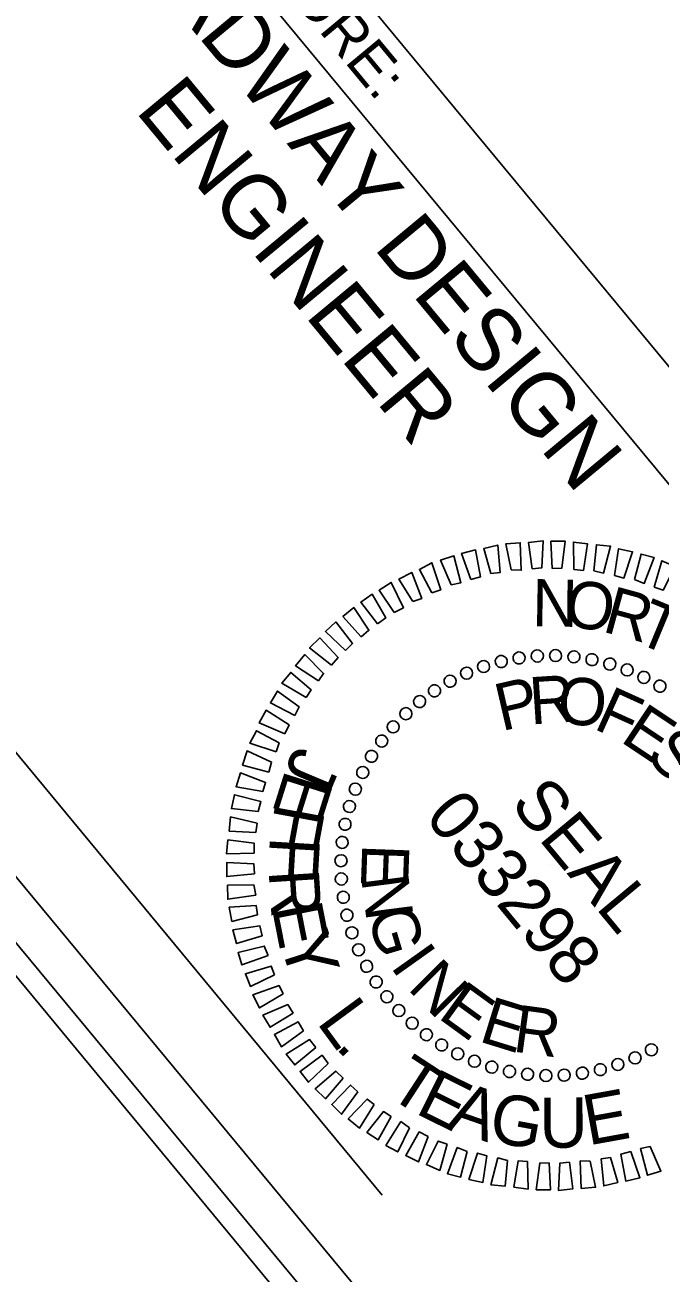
# Model space of a CAD drawing. Extents: x 2054826 to 2060231, y 685508 to 690809.
# Drawn here: x 2058686.8 to 2058800.7, y 687644.8 to 687868.3 of the extents above; entities that cross this region are included whole.
import ezdxf

# ---------------------------------------------------------------- set-up
doc = ezdxf.new("R2010")
doc.units = 0
for name, color, linetype in [('Sheet Plot Border Inside CELL', 7, 'Continuous'), ('Sheet Professional Seal CELL', 7, 'Continuous'), ('Sheet Title CELL', 7, 'Continuous')]:
    doc.layers.add(name, color=color, linetype=linetype)

msp = doc.modelspace()

# ---------------------------------------------------------------- linework, layer by layer
at = {"layer": 'Sheet Plot Border Inside CELL'}
msp.add_lwpolyline([(2057387.09, 689263.34), (2058982.75, 687339.12), (2060201.02, 688349.37), (2058605.36, 690273.59)], close=True, dxfattribs=at)
at = {"layer": 'Sheet Professional Seal CELL'}
for p, q in [((2058778.69, 687755.32), (2058778.69, 687755.32)), ((2058782, 687755.44), (2058782, 687755.44)), ((2058785.23, 687755.19), (2058785.23, 687755.19)), ((2058769.04, 687753.45), (2058769.04, 687753.45)), ((2058772.21, 687754.33), (2058772.21, 687754.33)), ((2058775.42, 687755.04), (2058775.42, 687755.04)), ((2058788.54, 687754.72), (2058788.54, 687754.72)), ((2058791.66, 687753.9), (2058791.66, 687753.9)), ((2058763.09, 687750.76), (2058763.09, 687750.76)), ((2058765.94, 687752.25), (2058765.94, 687752.25)), ((2058794.81, 687752.8), (2058794.81, 687752.8)), ((2058797.83, 687751.51), (2058797.83, 687751.51)), ((2058760.27, 687749.1), (2058760.27, 687749.1)), ((2058800.67, 687749.97), (2058800.67, 687749.97)), ((2058757.58, 687747.17), (2058757.58, 687747.17)), ((2058755.09, 687745.01), (2058755.09, 687745.01)), ((2058752.9, 687742.6), (2058752.9, 687742.6)), ((2058750.74, 687740.03), (2058750.74, 687740.03)), ((2058748.89, 687737.33), (2058748.89, 687737.33)), ((2058747.35, 687734.49), (2058747.35, 687734.49)), ((2058746.05, 687731.47), (2058746.05, 687731.47)), ((2058744.96, 687728.32), (2058744.96, 687728.32)), ((2058744.14, 687725.2), (2058744.14, 687725.2)), ((2058743.67, 687721.89), (2058743.67, 687721.89)), ((2058743.42, 687718.66), (2058743.42, 687718.66)), ((2058781.1, 687717.76), (2058781.1, 687717.76)), ((2058743.54, 687715.35), (2058743.54, 687715.35)), ((2058743.82, 687712.08), (2058743.82, 687712.08)), ((2058744.53, 687708.87), (2058744.53, 687708.87)), ((2058745.4, 687705.7), (2058745.4, 687705.7)), ((2058746.61, 687702.6), (2058746.61, 687702.6)), ((2058748.1, 687699.75), (2058748.1, 687699.75)), ((2058749.75, 687696.93), (2058749.75, 687696.93)), ((2058751.68, 687694.24), (2058751.68, 687694.24)), ((2058753.85, 687691.75), (2058753.85, 687691.75)), ((2058756.25, 687689.56), (2058756.25, 687689.56)), ((2058758.82, 687687.4), (2058758.82, 687687.4)), ((2058761.53, 687685.55), (2058761.53, 687685.55)), ((2058764.36, 687684.01), (2058764.36, 687684.01)), ((2058799.11, 687684.76), (2058799.11, 687684.76)), ((2058767.39, 687682.71), (2058767.39, 687682.71)), ((2058770.53, 687681.62), (2058770.53, 687681.62)), ((2058793.16, 687682.06), (2058793.16, 687682.06)), ((2058796.25, 687683.27), (2058796.25, 687683.27)), ((2058773.65, 687680.79), (2058773.65, 687680.79)), ((2058776.96, 687680.33), (2058776.96, 687680.33)), ((2058780.19, 687680.08), (2058780.19, 687680.08)), ((2058783.5, 687680.19), (2058783.5, 687680.19)), ((2058786.78, 687680.48), (2058786.78, 687680.48)), ((2058789.99, 687681.19), (2058789.99, 687681.19))]:
    msp.add_line(p, q, dxfattribs=at)
for points in [[(2058774, 687770.72), (2058773.06, 687775.39), (2058775.63, 687775.58), (2058775.81, 687770.66)], [(2058777.75, 687770.91), (2058777.13, 687775.65), (2058779.71, 687775.94), (2058779.47, 687771.07)], [(2058781.38, 687770.99), (2058781.14, 687775.86), (2058783.7, 687775.84), (2058783.09, 687771.05)], [(2058785.25, 687770.79), (2058785.17, 687775.7), (2058787.7, 687775.36), (2058786.94, 687770.64)], [(2058763.26, 687768.05), (2058761.33, 687772.49), (2058763.74, 687773.23), (2058765, 687768.42)], [(2058766.76, 687769), (2058765.12, 687773.68), (2058767.63, 687774.3), (2058768.51, 687769.48)], [(2058770.37, 687770.05), (2058769.09, 687774.54), (2058771.59, 687775.16), (2058772.04, 687770.27)], [(2058788.85, 687770.56), (2058789.28, 687775.21), (2058791.82, 687774.97), (2058790.57, 687770.14)], [(2058792.55, 687769.74), (2058793.27, 687774.52), (2058795.77, 687773.97), (2058794.21, 687769.26)], [(2058796.11, 687768.98), (2058797.28, 687773.56), (2058799.62, 687772.97), (2058797.85, 687768.29)], [(2058759.77, 687766.62), (2058757.55, 687770.82), (2058759.8, 687772), (2058761.37, 687767.16)], [(2058799.66, 687767.64), (2058801, 687772.36), (2058803.41, 687771.34), (2058801.26, 687767.11)], [(2058756.38, 687765.07), (2058753.87, 687769.03), (2058756.17, 687770.26), (2058757.97, 687765.62)], [(2058750.04, 687761.08), (2058747.04, 687764.93), (2058749.05, 687766.4), (2058751.52, 687762.12)], [(2058753.05, 687763.09), (2058750.33, 687767.07), (2058752.49, 687768.47), (2058754.68, 687763.95)], [(2058747.11, 687758.75), (2058743.82, 687762.36), (2058745.78, 687763.98), (2058748.49, 687759.9)], [(2058744.27, 687756.3), (2058740.69, 687759.67), (2058742.56, 687761.41), (2058745.56, 687757.56)], [(2058741.78, 687753.65), (2058737.86, 687756.73), (2058739.68, 687758.53), (2058742.98, 687755.03)], [(2058739.44, 687750.83), (2058735.33, 687753.56), (2058737.01, 687755.54), (2058740.37, 687752.19)], [(2058737.25, 687747.84), (2058732.86, 687750.44), (2058734.47, 687752.36), (2058738.12, 687749.25)], [(2058735.24, 687744.62), (2058730.82, 687746.9), (2058732.08, 687749.02), (2058735.98, 687746.2)], [(2058733.39, 687741.33), (2058728.83, 687743.3), (2058730.06, 687745.58), (2058734.18, 687742.96)], [(2058731.87, 687738.12), (2058727.16, 687739.68), (2058728.33, 687741.91), (2058732.39, 687739.72)], [(2058730.57, 687734.51), (2058725.84, 687735.75), (2058726.66, 687738.29), (2058731.05, 687736.28)], [(2058729.45, 687731.05), (2058724.68, 687731.87), (2058725.44, 687734.35), (2058729.97, 687732.65)], [(2058728.63, 687727.45), (2058723.83, 687727.95), (2058724.39, 687730.45), (2058729.12, 687729.21)], [(2058728.23, 687723.7), (2058723.46, 687723.94), (2058723.69, 687726.47), (2058728.43, 687725.34)], [(2058727.93, 687719.95), (2058722.97, 687719.83), (2058723.2, 687722.36), (2058727.89, 687721.77)], [(2058727.96, 687716.27), (2058723.01, 687715.78), (2058723.04, 687718.33), (2058727.86, 687718.04)], [(2058728.19, 687712.47), (2058723.17, 687711.71), (2058723.14, 687714.22), (2058727.83, 687714.31)], [(2058728.5, 687708.92), (2058723.92, 687707.75), (2058723.46, 687710.3), (2058728.28, 687710.6)], [(2058729.38, 687705.17), (2058724.77, 687703.79), (2058724.1, 687706.25), (2058728.96, 687706.96)], [(2058730.43, 687701.66), (2058725.69, 687699.97), (2058725.05, 687702.16), (2058729.74, 687703.32)], [(2058731.55, 687698.2), (2058727.25, 687696.1), (2058726.34, 687698.37), (2058730.95, 687699.75)], [(2058733.1, 687694.81), (2058728.86, 687692.27), (2058727.7, 687694.62), (2058732.38, 687696.26)], [(2058734.9, 687691.34), (2058730.78, 687688.79), (2058729.48, 687690.94), (2058733.93, 687692.87)], [(2058736.74, 687688.18), (2058732.79, 687685.3), (2058731.56, 687687.49), (2058735.82, 687689.76)], [(2058738.96, 687685.15), (2058735.21, 687682.04), (2058733.68, 687683.99), (2058737.87, 687686.59)], [(2058741.2, 687682.33), (2058737.69, 687678.93), (2058736.16, 687680.89), (2058740.11, 687683.77)], [(2058743.88, 687679.69), (2058740.71, 687675.99), (2058738.85, 687677.76), (2058742.56, 687680.93)], [(2058746.53, 687677.2), (2058743.6, 687673.21), (2058741.84, 687674.98), (2058745.2, 687678.44)], [(2058749.46, 687674.96), (2058746.83, 687670.73), (2058744.79, 687672.36), (2058748.16, 687675.93)], [(2058752.51, 687672.81), (2058750.14, 687668.61), (2058748.14, 687669.97), (2058751.1, 687673.69)], [(2058755.78, 687670.75), (2058753.67, 687666.47), (2058751.54, 687667.63), (2058754.23, 687671.9)], [(2058759.1, 687669.21), (2058757.39, 687664.68), (2058755.1, 687665.8), (2058757.52, 687670.05)], [(2058762.54, 687667.88), (2058761.19, 687663.16), (2058758.79, 687664.18), (2058760.94, 687668.4)], [(2058766.09, 687666.53), (2058764.92, 687661.96), (2058762.57, 687662.55), (2058764.34, 687667.23)], [(2058769.64, 687665.78), (2058768.93, 687661), (2058766.42, 687661.55), (2058767.98, 687666.25)], [(2058795.44, 687666.51), (2058797.08, 687661.83), (2058794.57, 687661.21), (2058793.69, 687666.04)], [(2058798.93, 687667.46), (2058800.86, 687663.02), (2058798.45, 687662.29), (2058797.19, 687667.09)], [(2058773.35, 687664.95), (2058772.91, 687660.3), (2058770.38, 687660.54), (2058771.63, 687665.38)], [(2058776.95, 687664.72), (2058777.02, 687659.81), (2058774.5, 687660.16), (2058775.26, 687664.88)], [(2058780.82, 687664.52), (2058781.05, 687659.65), (2058778.5, 687659.68), (2058779.11, 687664.47)], [(2058784.45, 687664.61), (2058785.07, 687659.86), (2058782.48, 687659.57), (2058782.73, 687664.45)], [(2058788.19, 687664.79), (2058789.14, 687660.12), (2058786.57, 687659.94), (2058786.39, 687664.85)], [(2058791.82, 687665.46), (2058793.11, 687660.98), (2058790.6, 687660.36), (2058790.15, 687665.25)]]:
    msp.add_lwpolyline(points, close=True, dxfattribs=at)
for centre, major_axis in [((2058772.21, 687754.31), (-0.26, 1.05)), ((2058775.43, 687754.95), (-0.16, 1.07)), ((2058778.69, 687755.3), (-0.07, 1.08)), ((2058781.97, 687755.37), (0.03, 1.08)), ((2058785.25, 687755.15), (0.12, 1.07)), ((2058788.49, 687754.64), (0.21, 1.06)), ((2058766, 687752.21), (-0.434, 0.989)), ((2058769.06, 687753.4), (-0.35, 1.02)), ((2058791.68, 687753.86), (0.3, 1.04)), ((2058794.78, 687752.8), (0.39, 1.01)), ((2058763.05, 687750.77), (-0.518, 0.948)), ((2058797.79, 687751.47), (0.479, 0.968)), ((2058800.66, 687749.89), (0.562, 0.922)), ((2058760.24, 687749.07), (-0.599, 0.899)), ((2058757.59, 687747.13), (-0.675, 0.843)), ((2058755.12, 687744.97), (-0.746, 0.781)), ((2058752.85, 687742.6), (-0.811, 0.713)), ((2058750.79, 687740.05), (-0.87, 0.64)), ((2058748.96, 687737.32), (-0.922, 0.562)), ((2058747.38, 687734.44), (-0.968, 0.479)), ((2058746.06, 687731.44), (-1.01, 0.39)), ((2058745, 687728.34), (-1.04, 0.3)), ((2058744.21, 687725.15), (-1.06, 0.21)), ((2058743.71, 687721.91), (-1.07, 0.12)), ((2058743.49, 687718.63), (-1.08, 0.03)), ((2058743.55, 687715.35), (-1.08, -0.07)), ((2058743.91, 687712.09), (-1.07, -0.16)), ((2058744.54, 687708.87), (-1.05, -0.26)), ((2058745.46, 687705.72), (-1.02, -0.35)), ((2058746.64, 687702.66), (-0.989, -0.434)), ((2058748.09, 687699.71), (-0.948, -0.518)), ((2058749.79, 687696.9), (-0.899, -0.599)), ((2058751.72, 687694.25), (-0.843, -0.675)), ((2058753.88, 687691.78), (-0.781, -0.746)), ((2058756.25, 687689.51), (-0.713, -0.811)), ((2058758.81, 687687.45), (-0.64, -0.87)), ((2058761.53, 687685.62), (-0.562, -0.922)), ((2058799.14, 687684.75), (0.518, -0.948)), ((2058764.41, 687684.04), (-0.479, -0.968)), ((2058767.41, 687682.71), (-0.39, -1.01)), ((2058796.2, 687683.3), (0.434, -0.989)), ((2058770.52, 687681.66), (-0.3, -1.04)), ((2058773.7, 687680.87), (-0.21, -1.06)), ((2058776.95, 687680.37), (-0.12, -1.07)), ((2058786.77, 687680.57), (0.16, -1.07)), ((2058789.99, 687681.2), (0.26, -1.05)), ((2058793.14, 687682.12), (0.35, -1.02)), ((2058780.22, 687680.15), (-0.03, -1.08)), ((2058783.5, 687680.21), (0.07, -1.08))]:
    msp.add_ellipse(centre, major_axis=major_axis, ratio=0.999708, dxfattribs=at)
at = {"layer": 'Sheet Title CELL'}
for p, q in [((2058714.94, 687912.46), (2058854.25, 687744.46)), ((2058699.6, 687909.89), (2058910.89, 687655.09)), ((2058611.54, 687826.74), (2058750.85, 687658.72))]:
    msp.add_line(p, q, dxfattribs=at)
for points in [[(2057547.07, 689076.42), (2058964.15, 687367.54)], [(2058606.09, 687811.11), (2058797.38, 687580.44)]]:
    msp.add_lwpolyline(points, dxfattribs=at)

# ---------------------------------------------------------------- texts
at = {"layer": 'Sheet Professional Seal CELL'}
for s, height, rotation, p in [('N', 8.46, 359.0907, (2058777.7, 687760.63)), ('O', 8.46, 351.8889, (2058783.25, 687760.75)), ('R', 8.46, 344.6877, (2058790.13, 687759.74)), ('T', 8.46, 337.487, (2058795.93, 687757.92)), ('P', 8.46, 13.0661, (2058772.26, 687741.8)), ('R', 8.46, 3.7069, (2058777.49, 687743.02)), ('O', 8.46, 354.3484, (2058781.99, 687743.35)), ('F', 8.46, 335.6342, (2058788.56, 687742.36)), ('E', 8.46, 326.2783, (2058793.36, 687740.1)), ('S', 8.46, 316.9228, (2058797.87, 687737.12)), ('J', 9, 247.2287, (2058735.38, 687739.46)), ('E', 9, 252.4865, (2058733.59, 687735.18)), ('SEAL', 8.997, 309.6672, (2058773.65, 687728.73)), ('033298', 8.997, 309.6672, (2058758.3, 687726.43)), ('F', 9, 259.5958, (2058731.8, 687729.17)), ('F', 9, 266.6124, (2058730.77, 687723.06)), ('E', 8.46, 267.9441, (2058747.32, 687721.71)), ('R', 9, 273.629, (2058730.5, 687716.87)), ('N', 8.46, 277.3012, (2058747.08, 687715.66)), ('E', 9, 281.1093, (2058731.05, 687710.29)), ('G', 8.46, 286.6574, (2058748.12, 687709.12)), ('Y', 9, 288.2186, (2058732.36, 687704.16)), ('I', 8.46, 305.3684, (2058752.2, 687699.74)), ('N', 8.46, 314.7236, (2058755.23, 687695.72)), ('E', 8.46, 324.079, (2058760.66, 687690.58)), ('L', 9, 306.332, (2058739, 687689.68)), ('E', 8.46, 342.7913, (2058767.99, 687686.33)), ('R', 8.46, 352.1486, (2058774.1, 687684.48)), ('.', 9, 312.6068, (2058742.32, 687685.24)), ('T', 9, 326.8409, (2058751.51, 687676.71)), ('E', 9, 333.6411, (2058756.58, 687673.49)), ('A', 9, 340.7505, (2058762.24, 687670.8)), ('G', 9, 349.5908, (2058769.68, 687668.46)), ('E', 9, 10.2542, (2058787.81, 687667.6)), ('U', 9, 0.3166, (2058779.06, 687667.19))]:
    msp.add_text(s, height=height, rotation=rotation, dxfattribs=at).set_placement(p)
at = {"layer": 'Sheet Title CELL'}
for s, height, p in [('SIGNATURE:', 7.499, (2058710.93, 687901.63)), ('ROADWAY DESIGN', 11.2491, (2058696.88, 687891.5)), ('ENGINEER', 11.249, (2058706.44, 687852.95))]:
    msp.add_text(s, height=height, rotation=309.6672, dxfattribs=at).set_placement(p)

doc.saveas('drawing.dxf')
